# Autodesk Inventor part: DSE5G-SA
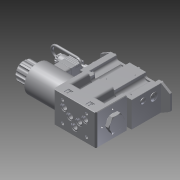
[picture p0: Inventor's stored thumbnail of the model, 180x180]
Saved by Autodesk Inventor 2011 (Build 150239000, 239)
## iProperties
Created: 2012-01
Part Number: DSE5G-SA
Document SubType Name: Modeling
Designer: khramov
Density: 1 g/cm^3
Author: khramov
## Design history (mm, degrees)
derived "DSE5G_C30SA_10N_E0K11_B.iam"
node "Твердое тело1"
node "0118966.ipt:1"
node "190301.ipt:1"
node "0119383.ipt:1"
sketch "0670792_.ipt:1"
sketch "0119459_CBL_5.ipt:1"
sketch "0672123_.ipt:1"
node "026973.ipt:1"
node "0134669.ipt:1"
node "0118964.ipt:1"
node "0118965.ipt:1"
sketch "3001620000.ipt:1"
sketch "0532082_UNI_5931___M3x12.ipt:1"
sketch "0532082_UNI_5931___M3x12.ipt:2"
sketch "0532082_UNI_5931___M3x12.ipt:3"
sketch "0532082_UNI_5931___M3x12.ipt:4"
sketch "0532082_UNI_5931___M3x12.ipt:5"
sketch "0532082_UNI_5931___M3x12.ipt:6"
node "0119458.ipt:1"
sketch "0532140_UNI_5931___M4x16.ipt:1"
sketch "0532140_UNI_5931___M4x16.ipt:2"
sketch "0532140_UNI_5931___M4x16.ipt:3"
sketch "0532140_UNI_5931___M4x16.ipt:4"
sketch "0680013.ipt:1"
sketch "0532085_UNI_5931___M3x8.ipt:1"
sketch "0532085_UNI_5931___M3x8.ipt:2"
sketch "0532085_UNI_5931___M3x8.ipt:3"
sketch "0532085_UNI_5931___M3x8.ipt:4"
sketch "0671191.ipt:1"
sketch "0671857.ipt:1"
node "0119457.ipt:1"
